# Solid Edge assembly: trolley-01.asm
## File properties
Title: Trolley Wheel Assembly
Subject: Trolley Wheel Assembly
Author: kiyo
Keywords: Assembly
Comments: Trolley Wheel Assembly
Template: metric.asm
Last saved by: edge
Revision: 38
Application: Solid Edge
File Size: 0
Number of Sheets: 0
Number of Objects: 0
Username: kiyo
文書内容のタイプ: 1
Document Number: TWA-101
Revision: 1
Project Name: Trolley Wheel Assembly
Category: Assembly
Manager: Brian Little
Company: Wheels R Us
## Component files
srwheel.par
chead.par
Splate.par
mtgpin.par
Wheel.asm
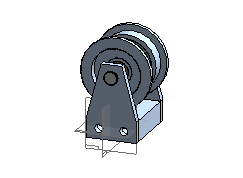
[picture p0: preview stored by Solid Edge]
